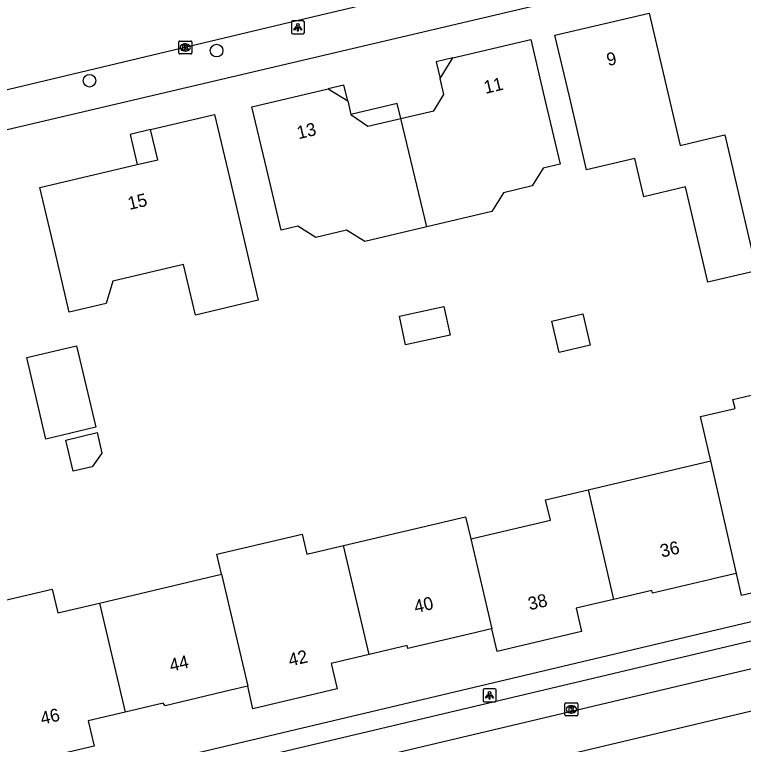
# Model space of a CAD drawing. Extents: x 158038 to 159242, y 380133 to 381214.
# Drawn here: x 158446.3 to 158502.6, y 380614.4 to 380670.9 of the extents above; entities that cross this region are included whole.
import ezdxf

# ---------------------------------------------------------------- set-up
doc = ezdxf.new("R2010")
doc.units = 0
for name, color, linetype in [('IMGEO_Boom', 7, 'Continuous'), ('IMGEO_Kolk', 7, 'Continuous'), ('IMGEO_Lichtpunt', 7, 'Continuous'), ('IMGEO_Pand', 7, 'Continuous'), ('IMGEO_Pand_nummerreeks', 7, 'Continuous'), ('IMGEO_Pand_overbouw', 7, 'Continuous'), ('IMGEO_Rijbaan_lokaal_gesloten', 7, 'Continuous'), ('IMGEO_Rijbaan_lokaal_open', 7, 'Continuous'), ('IMGEO_Voetpad_open', 7, 'Continuous')]:
    doc.layers.add(name, color=color, linetype=linetype)

msp = doc.modelspace()

# ---------------------------------------------------------------- linework, layer by layer
at = {"layer": 'IMGEO_Boom'}
for centre in [(158461.883, 380668.111), (158452.053, 380665.78)]:
    msp.add_circle(centre, 0.489, dxfattribs=at)
at = {"layer": 'IMGEO_Kolk'}
for p, q in [((158459.037, 380668.851), (158459.889, 380668.851)), ((158458.962, 380667.925), (158458.962, 380668.777)), ((158459.45, 380668.631), (158459.475, 380668.631)), ((158459.963, 380668.777), (158459.963, 380667.925)), ((158459.889, 380667.851), (158459.037, 380667.851)), ((158459.473, 380668.071), (158459.448, 380668.071)), ((158488.836, 380616.706), (158488.836, 380617.558)), ((158488.911, 380617.632), (158489.763, 380617.632)), ((158489.837, 380617.558), (158489.837, 380616.706)), ((158489.324, 380617.412), (158489.349, 380617.412)), ((158489.763, 380616.632), (158488.911, 380616.632)), ((158489.347, 380616.852), (158489.322, 380616.852))]:
    msp.add_line(p, q, dxfattribs=at)
for points in [[(158459.037, 380668.851), (158459.889, 380668.851)], [(158458.962, 380667.925), (158458.962, 380668.777)], [(158459.283, 380668.551), (158459.406, 380668.551), (158459.406, 380668.4), (158459.536, 380668.551), (158459.7, 380668.551), (158459.554, 380668.4), (158459.707, 380668.151), (158459.555, 380668.151), (158459.47, 380668.315), (158459.406, 380668.248), (158459.406, 380668.151), (158459.283, 380668.151), (158459.283, 380668.551)], [(158459.963, 380668.777), (158459.963, 380667.925)], [(158459.889, 380667.851), (158459.037, 380667.851)], [(158488.836, 380616.706), (158488.836, 380617.558)], [(158488.911, 380617.632), (158489.763, 380617.632)], [(158489.837, 380617.558), (158489.837, 380616.706)], [(158489.157, 380617.332), (158489.28, 380617.332), (158489.28, 380617.181), (158489.41, 380617.332), (158489.574, 380617.332), (158489.428, 380617.181), (158489.581, 380616.932), (158489.429, 380616.932), (158489.344, 380617.096), (158489.28, 380617.029), (158489.28, 380616.932), (158489.157, 380616.932), (158489.157, 380617.332)], [(158489.763, 380616.632), (158488.911, 380616.632)]]:
    msp.add_lwpolyline(points, dxfattribs=at)
for centre, start, end in [((158459.039, 380668.775), 91.552, 178.448), ((158459.039, 380668.775), 91.552, 178.448), ((158459.887, 380668.775), 1.552, 88.448), ((158459.887, 380668.775), 1.552, 88.448), ((158459.039, 380667.927), 181.552, 268.448), ((158459.039, 380667.927), 181.552, 268.448), ((158459.887, 380667.927), 271.552, 358.448), ((158459.887, 380667.927), 271.552, 358.448), ((158488.913, 380617.556), 91.552, 178.448), ((158488.913, 380617.556), 91.552, 178.448), ((158489.761, 380617.556), 1.552, 88.448), ((158489.761, 380617.556), 1.552, 88.448), ((158488.913, 380616.708), 181.552, 268.448), ((158488.913, 380616.708), 181.552, 268.448), ((158489.761, 380616.708), 271.552, 358.448), ((158489.761, 380616.708), 271.552, 358.448)]:
    msp.add_arc(centre, 0.0765, start, end, dxfattribs=at)
for centre, major_axis, ratio, start_param, end_param in [((158459.449, 380668.351), (-0.387, 0.002), 0.722429, 4.712389, 7.853982), ((158459.474, 380668.351), (-0.39, 0.002), 0.717154, 1.570796, 4.712389), ((158489.323, 380617.132), (-0.387, 0.002), 0.722429, 4.712389, 7.853982), ((158489.348, 380617.132), (-0.39, 0.002), 0.717154, 1.570796, 4.712389)]:
    msp.add_ellipse(centre, major_axis=major_axis, ratio=ratio, start_param=start_param, end_param=end_param, dxfattribs=at)
at = {"layer": 'IMGEO_Lichtpunt'}
for p, q in [((158467.677, 380670.312), (158467.677, 380669.505)), ((158467.677, 380670.312), (158467.677, 380669.505)), ((158468.579, 380670.407), (158467.771, 380670.407)), ((158468.579, 380670.407), (158467.771, 380670.407)), ((158468.673, 380669.505), (158468.673, 380670.312)), ((158468.673, 380669.505), (158468.673, 380670.312)), ((158467.771, 380669.411), (158468.579, 380669.411)), ((158467.771, 380669.411), (158468.579, 380669.411)), ((158482.507, 380618.622), (158482.507, 380617.815)), ((158482.507, 380618.622), (158482.507, 380617.815)), ((158483.409, 380618.717), (158482.601, 380618.717)), ((158483.409, 380618.717), (158482.601, 380618.717)), ((158483.503, 380617.815), (158483.503, 380618.622)), ((158483.503, 380617.815), (158483.503, 380618.622)), ((158482.601, 380617.721), (158483.409, 380617.721)), ((158482.601, 380617.721), (158483.409, 380617.721))]:
    msp.add_line(p, q, dxfattribs=at)
for points in [[(158468.051, 380669.976), (158468.09, 380669.948), (158467.902, 380669.686), (158467.864, 380669.713), (158468.051, 380669.976)], [(158468.153, 380669.928), (158468.2, 380669.928), (158468.2, 380669.606), (158468.153, 380669.606), (158468.153, 380669.928)], [(158468.263, 380669.948), (158468.301, 380669.975), (158468.488, 380669.713), (158468.449, 380669.685), (158468.263, 380669.948)], [(158482.881, 380618.286), (158482.92, 380618.258), (158482.732, 380617.996), (158482.694, 380618.023), (158482.881, 380618.286)], [(158482.983, 380618.238), (158483.03, 380618.238), (158483.03, 380617.916), (158482.983, 380617.916), (158482.983, 380618.238)], [(158483.093, 380618.258), (158483.131, 380618.285), (158483.318, 380618.023), (158483.279, 380617.995), (158483.093, 380618.258)]]:
    msp.add_lwpolyline(points, dxfattribs=at)
for centre in [(158468.176, 380670.11), (158483.006, 380618.42)]:
    msp.add_circle(centre, 0.0994, dxfattribs=at)
for centre, start, end in [((158467.771, 380670.312), 90, 180), ((158467.771, 380670.312), 90, 180), ((158468.579, 380670.312), 0, 90), ((158468.579, 380670.312), 0, 90), ((158467.771, 380669.505), 180, 270), ((158467.771, 380669.505), 180, 270), ((158468.579, 380669.505), 270, 0), ((158468.579, 380669.505), 270, 360), ((158482.601, 380618.622), 90, 180), ((158482.601, 380618.622), 90, 180), ((158483.409, 380618.622), 0, 90), ((158483.409, 380618.622), 0, 90), ((158482.601, 380617.815), 180, 270), ((158482.601, 380617.815), 180, 270), ((158483.409, 380617.815), 270, 0), ((158483.409, 380617.815), 270, 360)]:
    msp.add_arc(centre, 0.0946, start, end, dxfattribs=at)
at = {"layer": 'IMGEO_Pand'}
for points in [[(158498.156, 380657.558), (158494.937, 380656.807), (158494.246, 380659.768), (158490.495, 380658.892), (158489.2, 380664.444), (158488.064, 380669.313), (158495.347, 380671.012), (158497.735, 380660.777), (158500, 380661.306), (158501.196, 380661.585), (158502.332, 380656.716), (158503.649, 380651.073), (158500, 380650.219), (158499.875, 380650.189), (158498.156, 380657.558)], [(158476.135, 380662.86), (158478.682, 380663.46), (158479.462, 380664.722), (158479.171, 380665.96), (158480.148, 380667.54), (158486.194, 380668.963), (158487.339, 380664.096), (158488.462, 380659.326), (158487.148, 380659.017), (158486.294, 380657.636), (158484.078, 380657.115), (158483.17, 380655.648), (158478.152, 380654.466)], [(158478.152, 380654.466), (158473.343, 380653.334), (158471.927, 380654.21), (158469.562, 380653.653), (158468.173, 380654.513), (158466.872, 380654.207), (158465.768, 380658.899), (158464.622, 380663.765), (158470.521, 380665.154), (158472.028, 380664.222), (158472.277, 380663.166), (158473.589, 380662.261), (158476.135, 380662.86)], [(158465.113, 380648.79), (158460.25, 380647.645), (158459.329, 380651.558), (158453.855, 380650.269), (158453.332, 380648.532), (158450.487, 380647.862), (158449.36, 380652.647), (158448.214, 380657.513), (158455.75, 380659.288), (158457.331, 380659.66), (158456.781, 380661.998), (158461.729, 380663.163), (158462.875, 380658.297), (158465.113, 380648.79)], [(158478.152, 380654.466), (158476.135, 380662.86)], [(158479.949, 380646.088), (158476.511, 380645.337), (158476.026, 380647.557), (158479.464, 380648.308), (158479.949, 380646.088)], [(158490.23, 380647.743), (158490.797, 380645.321), (158488.375, 380644.754), (158487.808, 380647.176), (158490.23, 380647.743)], [(158452.539, 380638.961), (158448.682, 380638.052), (158447.199, 380644.352), (158451.056, 380645.26), (158452.539, 380638.961)], [(158500.128, 380636.359), (158500, 380636.906), (158499.323, 380639.797), (158500, 380639.956), (158501.99, 380640.422), (158501.825, 380641.122), (158505.768, 380642.046), (158506.726, 380637.955), (158509.617, 380638.634), (158510.467, 380635.01), (158511.608, 380630.142), (158508.537, 380629.422), (158508.995, 380627.467), (158502.483, 380625.94), (158502.098, 380627.643)], [(158452.26, 380635.912), (158450.782, 380635.564), (158450.213, 380637.976), (158452.636, 380638.547), (158453.01, 380636.963), (158452.26, 380635.912)], [(158490.618, 380634.129), (158500.128, 380636.359)], [(158502.098, 380627.643), (158500.128, 380636.359)], [(158481.55, 380630.323), (158481.676, 380630.353), (158482.212, 380630.479), (158487.709, 380631.775), (158487.337, 380633.36), (158490.618, 380634.129)], [(158490.618, 380634.129), (158492.594, 380625.648)], [(158471.711, 380629.82), (158481.149, 380632.043), (158481.55, 380630.323)], [(158462.275, 380627.589), (158461.908, 380629.147), (158468.509, 380630.703), (158468.875, 380629.151), (158471.711, 380629.82)], [(158481.55, 380630.323), (158483.17, 380623.37)], [(158473.681, 380621.372), (158471.711, 380629.82)], [(158502.098, 380627.643), (158501.859, 380627.587), (158500.31, 380627.224), (158500, 380627.151), (158495.615, 380626.122), (158495.564, 380626.341), (158492.594, 380625.648)], [(158452.837, 380625.366), (158462.275, 380627.589)], [(158462.275, 380627.589), (158464.294, 380618.924)], [(158454.805, 380616.922), (158451.943, 380616.248), (158452.404, 380614.29), (158445.678, 380612.706), (158444.531, 380617.573), (158443.619, 380621.444), (158442.8, 380624.929), (158443.481, 380625.943), (158444.642, 380626.217), (158445.431, 380625.549), (158449.164, 380626.428), (158449.593, 380624.602), (158452.837, 380625.366)], [(158452.837, 380625.366), (158454.805, 380616.922)], [(158492.594, 380625.648), (158489.693, 380624.971), (158490.121, 380623.153), (158483.58, 380621.612), (158483.17, 380623.37)], [(158483.17, 380623.37), (158482.914, 380623.31), (158481.862, 380623.062), (158476.69, 380621.844), (158476.637, 380622.069), (158473.681, 380621.372)], [(158473.681, 380621.372), (158470.757, 380620.683), (158471.219, 380618.722), (158464.699, 380617.186), (158464.294, 380618.924)], [(158464.294, 380618.924), (158464.072, 380618.872), (158462.966, 380618.611), (158457.919, 380617.422), (158457.74, 380617.613), (158454.805, 380616.922)]]:
    msp.add_lwpolyline(points, dxfattribs=at)
at = {"layer": 'IMGEO_Pand_overbouw'}
for points in [[(158480.148, 380667.54), (158478.87, 380667.239), (158479.171, 380665.96)], [(158470.521, 380665.154), (158472.028, 380664.222), (158471.74, 380665.441)], [(158475.859, 380664.009), (158472.277, 380663.166), (158473.589, 380662.261), (158476.135, 380662.86)], [(158456.781, 380661.998), (158455.198, 380661.626), (158455.75, 380659.288), (158457.331, 380659.66)]]:
    msp.add_lwpolyline(points, close=True, dxfattribs=at)
at = {"layer": 'IMGEO_Rijbaan_lokaal_gesloten'}
msp.add_lwpolyline([(158475.98, 380672.286), (158468.629, 380670.535), (158446.36, 380665.232), (158442.948, 380664.42), (158432.87, 380662.022), (158423.062, 380659.79), (158421.921, 380659.412), (158420.819, 380658.934), (158419.763, 380658.36), (158418.763, 380657.693), (158418.542, 380657.523), (158418.278, 380657.32), (158417.433, 380656.572), (158416.658, 380655.751), (158415.959, 380654.865)], dxfattribs=at)
at = {"layer": 'IMGEO_Rijbaan_lokaal_open'}
for points in [[(158508.189, 380621.442), (158421.707, 380600.951)], [(158424.178, 380598.251), (158506.752, 380617.853)]]:
    msp.add_lwpolyline(points, dxfattribs=at)
at = {"layer": 'IMGEO_Voetpad_open'}
for points in [[(158540.619, 380684.345), (158526.735, 380681.036), (158440.512, 380660.757)], [(158421.355, 380604.556), (158438.087, 380608.511), (158441.26, 380609.261), (158446.214, 380610.431), (158513.92, 380626.456), (158514.182, 380625.412), (158521.646, 380627.199), (158530.026, 380629.187), (158531.071, 380629.424)], [(158421.491, 380603.098), (158507.663, 380623.484), (158508.189, 380621.442)]]:
    msp.add_lwpolyline(points, dxfattribs=at)

# ---------------------------------------------------------------- texts
at = {"layer": 'IMGEO_Pand_nummerreeks'}
for s, rotation, p in [('9', 13.1313, (158492.182, 380666.906)), ('11', 13.3618, (158482.69, 380664.76)), ('13', 13.362, (158468.225, 380661.249)), ('15', 13.2514, (158455.144, 380655.776)), ('36', 13.2067, (158496.328, 380628.878)), ('38', 13.2525, (158486.106, 380624.796)), ('40', 13.2525, (158477.287, 380624.574)), ('42', 13.2525, (158467.567, 380620.45)), ('44', 13.2582, (158458.365, 380620.035)), ('46', 13.2525, (158448.386, 380615.933))]:
    msp.add_text(s, height=1, rotation=rotation, dxfattribs=at).set_placement(p)

doc.saveas('drawing.dxf')
